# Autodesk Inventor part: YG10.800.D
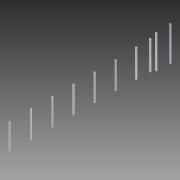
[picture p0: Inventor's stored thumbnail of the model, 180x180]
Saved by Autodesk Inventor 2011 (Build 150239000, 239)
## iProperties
Created: 2014-05
Part Number: YG10.800.D
Document SubType Name: Modeling
Designer: Evgeny
Density: 1 g/cm^3
Author: Evgeny
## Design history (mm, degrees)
sketch "Эскиз2"
  geometry: C1 r 4 at (0, 0); C2 r 3 at (0, 0); C3 r 4 at (0, -75); C4 r 3 at (0, -75); C5 r 4 at (0, 32); C6 r 3 at (0, 32); C7 r 4 at (0, 107); C8 r 3 at (0, 107); C9 r 4 at (0, 217); C10 r 3 at (0, 217); C11 r 3 at (0, 329); C12 r 4 at (0, 329); C13 r 3 at (0, 442); C14 r 4 at (0, 442); C15 r 3 at (0, 556); C16 r 4 at (0, 556); C17 r 3 at (0, 670); C18 r 4 at (0, 670); C19 r 3 at (0, 783); C20 r 4 at (0, 783); 1 further point
  constraints: 20 centre point, 11 coincident
  dimensions: "d0" = 8 diameter of C1; "d1" = 6 diameter of C2; "d2" = 8 diameter of C3; "d3" = 6 diameter of C4; "d4" = 8 diameter of C5; "d5" = 6 diameter of C6; "d6" = 75 distance of C3.centre point (0, 0); "d7" = 32 distance of C6.centre point (0, 0); "d8" = 8 diameter of C7; "d9" = 6 diameter of C8; "d10" = 8 diameter of C9; "d11" = 6 diameter of C10; "d12" = 75 distance of C8.centre C6.centre; "d13" = 110 distance of C10.centre C8.centre; "d14" = 8 diameter of C12; "d15" = 6 diameter of C11; "d16" = 112 distance of C11.centre C10.centre; "d17" = 8 diameter of C14; "d18" = 6 diameter of C13; "d19" = 113 distance of C13.centre C11.centre; "d20" = 8 diameter of C16; "d21" = 6 diameter of C15; "d22" = 114 distance of C15.centre C13.centre; "d23" = 8 diameter of C18; "d24" = 6 diameter of C17; "d25" = 114 distance of C17.centre C15.centre; "d26" = 8 diameter of C20; "d27" = 6 diameter of C19; "d28" = 113 distance of C20.centre C17.centre
extrude "Выдавливание1" new body sketch "Эскиз2" stored distance "d29" = 184; taper "d30" = 0 deg
extrude "Выдавливание2" join sketch "Эскиз2" stored distance "d31" = 175; taper "d32" = 0 deg
extrude "Выдавливание3" join sketch "Эскиз2" stored distance "d33" = 153.5; taper "d34" = 0 deg
extrude "Выдавливание4" join sketch "Эскиз2" stored distance "d35" = 148; taper "d36" = 0 deg
extrude "Выдавливание5" join sketch "Эскиз2" stored distance "d37" = 142; taper "d38" = 0 deg
extrude "Выдавливание6" join sketch "Эскиз2" stored distance "d39" = 141; taper "d40" = 0 deg
extrude "Выдавливание7" join sketch "Эскиз2" stored distance "d41" = 142; taper "d42" = 0 deg
extrude "Выдавливание8" join sketch "Эскиз2" stored distance "d43" = 140; taper "d44" = 0 deg
extrude "Выдавливание9" join sketch "Эскиз2" stored distance "d45" = 142; taper "d46" = 0 deg
extrude "Выдавливание10" join sketch "Эскиз2" stored distance "d47" = 134; taper "d48" = 0 deg
sketch "Эскиз3"
  geometry: L1 (1, 8)-(-1, 8); L2 (-1, 8)-(-1, -8); L3 (-1, -8)-(1, -8); L4 (1, -8)-(1, 8); 1 further point
  constraints: 8 end point, 2 parallel, 1 horizontal, 1 perpendicular
  dimensions: "d49" = 2 distance between parallel lines of L2 L4; "d50" = 1 distance from line of L2 point (0, 0); "d51" = 8 distance from line of L1 point (0, 0); "d52" = 16 distance between parallel lines of L3 L1
extrude "Выдавливание11" cut sketch "Эскиз3" stored distance "d53" = 10; taper "d54" = 0 deg
node "Твердое тело1"
